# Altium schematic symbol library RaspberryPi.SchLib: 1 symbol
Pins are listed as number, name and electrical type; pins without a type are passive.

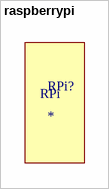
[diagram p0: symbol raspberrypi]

## raspberrypi
designator RPi?
footprint raspberrypi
